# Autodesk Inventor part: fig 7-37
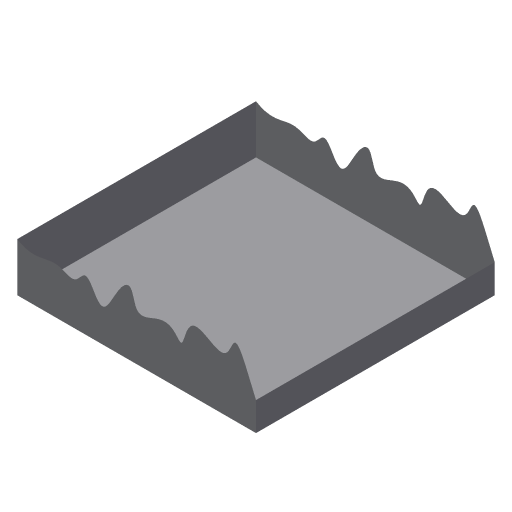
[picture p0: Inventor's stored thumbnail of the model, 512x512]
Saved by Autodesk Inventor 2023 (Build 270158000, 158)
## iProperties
Part Number: fig 7-37
Document SubType Name: Modeling
Created: 2002-12
Designer: deepak
Density: 1 g/cm^3
Material: Generic
Appearance: Default
Control State: 0
Master: False
Checked Out: False
Shininess: 64.0
Length Units: 11269
Angle Units: 11279
Time Units: 11290
Mass Units: 11283
Length Display Precision: 3
Angle Display Precision: 2
Compacted: True
Density: 0.0
Volumn: 0.0
Area: 0.0
PropertySet Name: Model Information
Author: deepak
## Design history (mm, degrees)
sketch "Sketch1"
  geometry: L1 (-32.188, 30.089)-(27.812, 30.089); L2 (27.812, 30.089)-(27.812, -29.911); L3 (27.812, -29.911)-(-32.188, -29.911); L4 (-32.188, -29.911)-(-32.188, 30.089)
  constraints: 8 end point, 2 parallel, 1 horizontal, 1 perpendicular
  dimensions: "d0" = 60 distance of L1.start L1.end; "d1" = 60 distance of L3.end L1.start
extrude "Extrusion1" new body sketch "Sketch1" stored distance "d2" = 20; taper "d3" = 0 deg
sketch "Sketch2"
  geometry: 17 further points
  constraints: 17 other
extrude_surface "ExtrusionSrf1" sketch "Sketch2" dims "d4" = 70, "d5" = 0
split "Split1"
delete_face "Delete Face1"
node "Sketch5"
body "Srf1"
body "Srf2"
